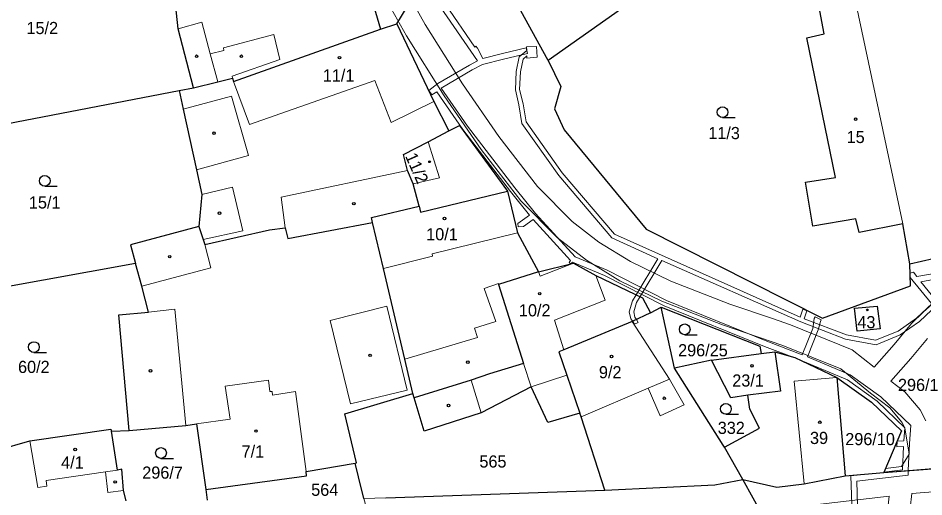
# Model space of a CAD drawing. Extents: x -769392 to -767038, y -1018329 to -1015269.
# Drawn here: x -768574.3 to -768447.4, y -1016273.5 to -1016206.6 of the extents above; entities that cross this region are included whole.
import ezdxf
from ezdxf.enums import TextEntityAlignment as Align

# ---------------------------------------------------------------- set-up
doc = ezdxf.new("R2010")
doc.units = 0
doc.header["$LTSCALE"] = 0.68
for name, color, linetype, lineweight in [('1', 7, 'Continuous', 25), ('13', 7, 'Continuous', 13), ('3', 7, 'Continuous', 25), ('4', 7, 'Continuous', 13), ('5', 7, 'Continuous', 25)]:
    doc.layers.add(name, color=color, linetype=linetype, lineweight=lineweight)
doc.layers.add('2', color=7, linetype='Continuous')

msp = doc.modelspace()

# ---------------------------------------------------------------- linework, layer by layer
at = {"layer": '1'}
for p, q in [((-768464.56, -1016187.45), (-768500.05, -1016212.5)), ((-768500.05, -1016212.5), (-768508.98, -1016196.12)), ((-768551.88, -1016208.04), (-768552.72, -1016199.41)), ((-768521.22, -1016207.35), (-768516.86, -1016200.1)), ((-768525.24, -1016202.34), (-768523.51, -1016208.11)), ((-768461.37, -1016208.75), (-768462.15, -1016204.79)), ((-768523.51, -1016208.11), (-768521.22, -1016207.35)), ((-768521.22, -1016207.35), (-768516.06, -1016218.21)), ((-768549.7, -1016216.3), (-768551.88, -1016208.04)), ((-768544.13, -1016215.41), (-768523.51, -1016208.11)), ((-768463.8, -1016209.3), (-768461.37, -1016208.75)), ((-768459.8, -1016228.85), (-768463.8, -1016209.3)), ((-768500.05, -1016212.5), (-768498.27, -1016216.11)), ((-768546.32, -1016215.48), (-768544.23, -1016214.97)), ((-768544.23, -1016214.97), (-768544.13, -1016215.41)), ((-768551.7, -1016216.69), (-768549.7, -1016216.3)), ((-768549.7, -1016216.3), (-768546.32, -1016215.48)), ((-768498.27, -1016216.11), (-768499.15, -1016219.23)), ((-768592.42, -1016224.53), (-768551.7, -1016216.69)), ((-768551.7, -1016216.69), (-768551.14, -1016219.28)), ((-768516.06, -1016218.21), (-768513.97, -1016222.32)), ((-768551.14, -1016219.28), (-768549.3, -1016227.76)), ((-768499.15, -1016219.23), (-768497.79, -1016222.2)), ((-768516.82, -1016223.86), (-768513.97, -1016222.32)), ((-768513.97, -1016222.32), (-768512.44, -1016221.6)), ((-768512.44, -1016221.6), (-768505.74, -1016230.76)), ((-768497.79, -1016222.2), (-768486.31, -1016236.1)), ((-768520.3, -1016225.66), (-768516.82, -1016223.86)), ((-768519.75, -1016227.87), (-768520.3, -1016225.66)), ((-768549.3, -1016227.76), (-768548.56, -1016231.25)), ((-768518.93, -1016229.73), (-768519.75, -1016227.87)), ((-768463.98, -1016229.5), (-768459.8, -1016228.85)), ((-768518.12, -1016232.87), (-768518.93, -1016229.73)), ((-768462.96, -1016235.68), (-768463.98, -1016229.5)), ((-768548.56, -1016231.25), (-768548.94, -1016235.73)), ((-768517.91, -1016233.72), (-768505.74, -1016230.76)), ((-768505.74, -1016230.76), (-768504.34, -1016236.59)), ((-768524.8, -1016234.47), (-768518.12, -1016232.87)), ((-768518.12, -1016232.87), (-768517.91, -1016233.72)), ((-768536.52, -1016237.38), (-768524.66, -1016235.14)), ((-768524.66, -1016235.14), (-768524.8, -1016234.47)), ((-768523.12, -1016241.57), (-768524.66, -1016235.14)), ((-768456.94, -1016234.65), (-768462.96, -1016235.68)), ((-768456.49, -1016236.57), (-768456.94, -1016234.65)), ((-768548.94, -1016235.73), (-768558.51, -1016238.26)), ((-768548.94, -1016235.73), (-768548.36, -1016237.55)), ((-768548.14, -1016238.23), (-768539.08, -1016236.16)), ((-768539.08, -1016236.16), (-768536.88, -1016235.89)), ((-768536.88, -1016235.89), (-768536.52, -1016237.38)), ((-768504.34, -1016236.59), (-768501.37, -1016242.06)), ((-768486.31, -1016236.1), (-768461.6, -1016248.53)), ((-768450.36, -1016235.36), (-768456.49, -1016236.57)), ((-768449.37, -1016240.92), (-768450.36, -1016235.36)), ((-768548.36, -1016237.55), (-768548.14, -1016238.23)), ((-768558.51, -1016238.26), (-768557.84, -1016240.9)), ((-768449.37, -1016240.92), (-768441.25, -1016239.08)), ((-768557.84, -1016240.9), (-768589.35, -1016246.59)), ((-768556.95, -1016244.04), (-768557.84, -1016240.9)), ((-768520.12, -1016254.29), (-768523.12, -1016241.57)), ((-768501.37, -1016242.06), (-768496.48, -1016240.86)), ((-768496.48, -1016240.86), (-768493.37, -1016242.55)), ((-768449.31, -1016244), (-768449.37, -1016240.92)), ((-768501.37, -1016242.06), (-768506.97, -1016243.83)), ((-768493.37, -1016242.55), (-768486.82, -1016245.68)), ((-768556, -1016247.72), (-768556.95, -1016244.04)), ((-768506.97, -1016243.83), (-768503.51, -1016254.88)), ((-768461.6, -1016248.53), (-768449.31, -1016244)), ((-768486.82, -1016245.68), (-768485.71, -1016247.77)), ((-768560.19, -1016248.07), (-768556, -1016247.72)), ((-768485.71, -1016247.77), (-768488.26, -1016249.01)), ((-768485.71, -1016247.77), (-768484.23, -1016247)), ((-768482.36, -1016255.54), (-768484.23, -1016247)), ((-768484.23, -1016247), (-768470.39, -1016252.44)), ((-768457.11, -1016247.14), (-768453.94, -1016246.86)), ((-768456.77, -1016250.36), (-768457.11, -1016247.14)), ((-768453.94, -1016246.86), (-768453.53, -1016250.04)), ((-768558.72, -1016264.24), (-768560.19, -1016248.07)), ((-768488.26, -1016249.01), (-768497.82, -1016252.96)), ((-768453.53, -1016250.04), (-768456.77, -1016250.36)), ((-768497.82, -1016252.96), (-768498.52, -1016253.25)), ((-768470.39, -1016252.44), (-768470.19, -1016253.48)), ((-768518.99, -1016259.09), (-768520.12, -1016254.29)), ((-768498.52, -1016253.25), (-768497.4, -1016256.52)), ((-768477.14, -1016254.4), (-768470.19, -1016253.48)), ((-768470.19, -1016253.48), (-768468.3, -1016253.25)), ((-768468.3, -1016253.25), (-768465.47, -1016254.05)), ((-768468.3, -1016253.25), (-768467.52, -1016258.75)), ((-768465.47, -1016254.05), (-768459.62, -1016256.85)), ((-768503.51, -1016254.88), (-768508.27, -1016256.32)), ((-768477.14, -1016254.4), (-768482.36, -1016255.54)), ((-768475.52, -1016266.32), (-768482.36, -1016255.54)), ((-768474.43, -1016259.66), (-768477.14, -1016254.4)), ((-768508.27, -1016256.32), (-768510.83, -1016257.2)), ((-768497.4, -1016256.52), (-768495.58, -1016261.82)), ((-768459.62, -1016256.85), (-768458.42, -1016270.59)), ((-768459.62, -1016256.85), (-768454.76, -1016260.29)), ((-768510.83, -1016257.2), (-768518.82, -1016259.7)), ((-768502.44, -1016258.14), (-768509.41, -1016261.8)), ((-768500.06, -1016263.13), (-768502.44, -1016258.14)), ((-768528.52, -1016261.93), (-768518.99, -1016259.09)), ((-768518.82, -1016259.7), (-768518.99, -1016259.09)), ((-768472.06, -1016259.32), (-768474.43, -1016259.66)), ((-768467.52, -1016258.75), (-768472.06, -1016259.32)), ((-768471.81, -1016261.28), (-768472.06, -1016259.32)), ((-768517.38, -1016264.36), (-768518.82, -1016259.7)), ((-768454.76, -1016260.29), (-768450.56, -1016264.31)), ((-768526.87, -1016268.77), (-768528.52, -1016261.93)), ((-768509.41, -1016261.8), (-768517.38, -1016264.36)), ((-768495.58, -1016261.82), (-768500.06, -1016263.13)), ((-768495.4, -1016262.34), (-768495.58, -1016261.82)), ((-768470.45, -1016263.93), (-768471.81, -1016261.28)), ((-768492.08, -1016272.62), (-768495.4, -1016262.34)), ((-768572.62, -1016265.7), (-768561.29, -1016264.07)), ((-768561.29, -1016264.07), (-768561.2, -1016264.37)), ((-768561.2, -1016264.37), (-768558.72, -1016264.24)), ((-768560.34, -1016269.81), (-768561.2, -1016264.37)), ((-768558.72, -1016264.24), (-768550.8, -1016263.56)), ((-768550.8, -1016263.56), (-768549.28, -1016263.33)), ((-768549.28, -1016263.33), (-768547.99, -1016272.52)), ((-768475.36, -1016266.59), (-768470.45, -1016263.93)), ((-768450.56, -1016264.31), (-768453.04, -1016270.15)), ((-768586.47, -1016269.73), (-768572.62, -1016265.7)), ((-768475.36, -1016266.59), (-768475.52, -1016266.32)), ((-768472.78, -1016271.11), (-768475.36, -1016266.59)), ((-768533.93, -1016269.99), (-768527.06, -1016268.82)), ((-768527.06, -1016268.82), (-768526.87, -1016268.77)), ((-768526.59, -1016270.75), (-768527.06, -1016268.82)), ((-768453.04, -1016270.15), (-768438.59, -1016268.98)), ((-768559.76, -1016269.68), (-768560.34, -1016269.81)), ((-768559.49, -1016272.66), (-768559.76, -1016269.68)), ((-768547.99, -1016272.52), (-768533.86, -1016270.61)), ((-768533.86, -1016270.61), (-768533.93, -1016269.99)), ((-768525.85, -1016273.77), (-768526.59, -1016270.75)), ((-768464.2, -1016271.71), (-768458.42, -1016270.59)), ((-768458.42, -1016270.59), (-768453.04, -1016270.15)), ((-768492.08, -1016272.62), (-768476.68, -1016271.84)), ((-768476.68, -1016271.84), (-768472.78, -1016271.11)), ((-768472.78, -1016271.11), (-768468.02, -1016272.16)), ((-768469.86, -1016276.35), (-768472.78, -1016271.11)), ((-768468.02, -1016272.16), (-768464.2, -1016271.71)), ((-768559.15, -1016274.1), (-768559.49, -1016272.66)), ((-768547.99, -1016272.52), (-768547.78, -1016273.99)), ((-768522.75, -1016273.66), (-768498.76, -1016272.82)), ((-768498.76, -1016272.82), (-768492.08, -1016272.62))]:
    msp.add_line(p, q, dxfattribs=at)
at = {"layer": '13'}
for points in [[(-768506.93, -1016223.11), (-768512.05, -1016215.74), (-768517.25, -1016207.46), (-768520.98, -1016200.75), (-768527.01, -1016190.22), (-768528.22, -1016188.66), (-768532.37, -1016182.87), (-768540.52, -1016173.96), (-768546.13, -1016167.31), (-768546.34, -1016166.87), (-768548.49, -1016162.47), (-768548.7, -1016152.45), (-768551.52, -1016145.96), (-768556.22, -1016138.29), (-768560.24, -1016130.3), (-768565.36, -1016119.48), (-768569.27, -1016111.41), (-768572.99, -1016103.31), (-768575.19, -1016097.78), (-768577.71, -1016091.86), (-768578.82, -1016089.6), (-768579.58, -1016087.11), (-768582.55, -1016087.86)], [(-768523.65, -1016202.25), (-768519.89, -1016209.02), (-768514.61, -1016217.44), (-768509.41, -1016224.92), (-768503.87, -1016232.12), (-768498.72, -1016237.29), (-768494.69, -1016240.44), (-768489.98, -1016243.31), (-768484.1, -1016246.16), (-768475.62, -1016249.47), (-768467.19, -1016252.34), (-768459.03, -1016255.63), (-768454.9, -1016259.05), (-768452.19, -1016261.07), (-768450.49, -1016263.09), (-768450.06, -1016263.88), (-768449.49, -1016267.55), (-768450.54, -1016269.3), (-768452.78, -1016269.55), (-768453.04, -1016270.15), (-768438.59, -1016268.98)], [(-768515.11, -1016205.02), (-768509.94, -1016212.51), (-768511.07, -1016213.12), (-768515.49, -1016215.7), (-768516.77, -1016216.66), (-768516.31, -1016217.28), (-768515.63, -1016216.87), (-768511.99, -1016222.14), (-768505.32, -1016230.8), (-768502.65, -1016234.11), (-768504.28, -1016235.3), (-768504.24, -1016235.78), (-768503.5, -1016235.72), (-768502.14, -1016234.72), (-768496.89, -1016240.46), (-768497.1, -1016240.75), (-768496.84, -1016240.94), (-768496.65, -1016240.68), (-768492.13, -1016242.57), (-768483.8, -1016246.8), (-768469.72, -1016252.48), (-768466.23, -1016253.83), (-768465.47, -1016254.05), (-768464.58, -1016254.48), (-768464.39, -1016254.55), (-768458.12, -1016257.17), (-768453.97, -1016260.17), (-768450.08, -1016263.88), (-768450.2, -1016265.68), (-768451.17, -1016265.74), (-768451.18, -1016265.77), (-768451.2, -1016266.54), (-768450.25, -1016266.49), (-768450.39, -1016269.77), (-768453.01, -1016270.08), (-768453.04, -1016270.15), (-768449.6, -1016269.87), (-768449.43, -1016266.08), (-768449.26, -1016263.56), (-768453.45, -1016259.56), (-768457.73, -1016256.47), (-768463.72, -1016253.96), (-768462.22, -1016250.19), (-768461.9, -1016248.98), (-768461.79, -1016248.76), (-768462.66, -1016248.33), (-768462.77, -1016248.56), (-768462.99, -1016249.97), (-768464.46, -1016253.66), (-768469.43, -1016251.74), (-768483.47, -1016246.07), (-768491.79, -1016241.84), (-768496.27, -1016239.95), (-768501.82, -1016233.88), (-768504.69, -1016230.31), (-768511.34, -1016221.66), (-768515.02, -1016216.35), (-768510.68, -1016213.81), (-768509.21, -1016213.03), (-768506.29, -1016212.31), (-768502.94, -1016211.49), (-768503.13, -1016210.71), (-768506.43, -1016211.52), (-768509.19, -1016212.19), (-768509.95, -1016210.76), (-768510.16, -1016210.5), (-768510.29, -1016210.6), (-768514.46, -1016204.55)], [(-768443.36, -1016243.78), (-768448.43, -1016248.53), (-768451.04, -1016250.36), (-768454.18, -1016251.63), (-768458.24, -1016250.88), (-768464.16, -1016248.61), (-768463.79, -1016247.5), (-768464.35, -1016247.28), (-768464.72, -1016248.38), (-768490.75, -1016236.8), (-768498.08, -1016228.2), (-768503.14, -1016221.08), (-768503.56, -1016218.56), (-768504.03, -1016216.52), (-768503.93, -1016214.09), (-768503.55, -1016212.29), (-768503.01, -1016211.85), (-768503.01, -1016212.14), (-768501.58, -1016212.04), (-768501.68, -1016210.51), (-768503.05, -1016210.58), (-768503.03, -1016211.09), (-768504.09, -1016211.96), (-768504.52, -1016214.02), (-768504.63, -1016216.57), (-768504.15, -1016218.68), (-768503.71, -1016221.31), (-768498.55, -1016228.57), (-768491.11, -1016237.29), (-768484.68, -1016240.25), (-768487.71, -1016245.25), (-768487.17, -1016245.51), (-768484.13, -1016240.49), (-768464.64, -1016249.06), (-768458.4, -1016251.46), (-768454.11, -1016252.25), (-768450.75, -1016250.89), (-768448.05, -1016249), (-768442.98, -1016244.25)], [(-768445.06, -1016245.52), (-768447.47, -1016247.67), (-768449.15, -1016249.27), (-768451.57, -1016252.22), (-768454.36, -1016255.38), (-768457.48, -1016252.95), (-768466.11, -1016249.48), (-768468.64, -1016248.58), (-768474.58, -1016246.59), (-768482.87, -1016243.36), (-768488.51, -1016240.61), (-768492.95, -1016237.92), (-768496.68, -1016234.99), (-768501.55, -1016230.1), (-768506.93, -1016223.11)], [(-768442.41, -1016241.66), (-768448.42, -1016242.72), (-768448.89, -1016242.11), (-768449.34, -1016242.22), (-768449.33, -1016242.84), (-768446.37, -1016246.5)], [(-768445.77, -1016245.98), (-768447.85, -1016243.43), (-768442.23, -1016242.44)], [(-768447.12, -1016262.9), (-768447.95, -1016261.35), (-768450.07, -1016258.83), (-768452.03, -1016257.37), (-768449.23, -1016254.2), (-768446.9, -1016251.36)], [(-768438.59, -1016268.98), (-768453.04, -1016270.15), (-768458.42, -1016270.59), (-768464.2, -1016271.71), (-768468.02, -1016272.16), (-768472.78, -1016271.11), (-768470.32, -1016275.52), (-768452.26, -1016273.45), (-768452.82, -1016278.43), (-768450.31, -1016295.22), (-768450.12, -1016319.52), (-768449.71, -1016331.77), (-768449.58, -1016335.6), (-768448.17, -1016335.38), (-768448.24, -1016327), (-768448.89, -1016315.19), (-768449.5, -1016298.7), (-768449.71, -1016295.97), (-768450.07, -1016285.71), (-768449.8, -1016279.21), (-768449.1, -1016273.07), (-768429.05, -1016271.47)], [(-768456.66, -1016276.52), (-768456.82, -1016271.33), (-768449.63, -1016270.49), (-768449.6, -1016269.87), (-768453.04, -1016270.15), (-768454.99, -1016270.31), (-768457.64, -1016270.62), (-768457.47, -1016275.91)]]:
    msp.add_lwpolyline(points, dxfattribs=at)
for points in [[(-768488.68, -1016247.66), (-768488.44, -1016248.63), (-768488.2, -1016248.98), (-768487.68, -1016248.73), (-768487.88, -1016248.41), (-768488.06, -1016247.67), (-768487.67, -1016246.33), (-768487.17, -1016245.51), (-768487.71, -1016245.25), (-768488.22, -1016246.09)], [(-768487.96, -1016249.38), (-768487.44, -1016249.12), (-768487.68, -1016248.73), (-768488.2, -1016248.98), (-768488.12, -1016249.1)], [(-768488.6, -1016275.46), (-768471.55, -1016275.66), (-768470.32, -1016275.52), (-768472.78, -1016271.11), (-768476.68, -1016271.84), (-768492.08, -1016272.62), (-768498.76, -1016272.82), (-768522.75, -1016273.66), (-768525.85, -1016273.77), (-768525.07, -1016276.6), (-768517.45, -1016276.37)]]:
    msp.add_lwpolyline(points, close=True, dxfattribs=at)
at = {"layer": '3'}
for p, q in [((-768475.613, -1016220.47), (-768473.863, -1016220.47)), ((-768570.543, -1016230.07), (-768568.793, -1016230.07)), ((-768480.913, -1016250.85), (-768479.163, -1016250.85)), ((-768572.063, -1016253.33), (-768570.313, -1016253.33)), ((-768475.143, -1016261.98), (-768473.393, -1016261.98)), ((-768554.263, -1016268.15), (-768552.513, -1016268.15))]:
    msp.add_line(p, q, dxfattribs=at)
for centre in [(-768475.6129, -1016219.7198), (-768570.5429, -1016229.3198), (-768480.9129, -1016250.0998), (-768572.0629, -1016252.5798), (-768475.1429, -1016261.2298), (-768554.2629, -1016267.3998)]:
    msp.add_circle(centre, 0.75, dxfattribs=at)
at = {"layer": '4'}
for p, q in [((-768457.02, -1016203.95), (-768450.36, -1016235.36)), ((-768551.88, -1016208.04), (-768548.54, -1016207.1)), ((-768548.54, -1016207.1), (-768547.36, -1016211.56)), ((-768545.53, -1016210.7), (-768538.46, -1016208.86)), ((-768538.46, -1016208.86), (-768537.64, -1016212.33)), ((-768547.36, -1016211.56), (-768545.48, -1016211.1)), ((-768545.48, -1016211.1), (-768545.53, -1016210.7)), ((-768547.36, -1016211.56), (-768546.32, -1016215.48)), ((-768537.64, -1016212.33), (-768544.31, -1016214.67)), ((-768544.31, -1016214.67), (-768544.23, -1016214.97)), ((-768544.13, -1016215.41), (-768541.85, -1016221.43)), ((-768541.85, -1016221.43), (-768524.3, -1016215.26)), ((-768524.3, -1016215.26), (-768522.02, -1016221.16)), ((-768544.39, -1016217.47), (-768551.14, -1016219.28)), ((-768541.99, -1016225.8), (-768544.39, -1016217.47)), ((-768522.02, -1016221.16), (-768516.06, -1016218.21)), ((-768516.82, -1016223.86), (-768515.25, -1016228.91)), ((-768549.3, -1016227.76), (-768541.99, -1016225.8)), ((-768519.75, -1016227.87), (-768537.43, -1016231.63)), ((-768515.25, -1016228.91), (-768518.93, -1016229.73)), ((-768544.23, -1016230.23), (-768548.56, -1016231.25)), ((-768542.82, -1016236.31), (-768544.23, -1016230.23)), ((-768537.43, -1016231.63), (-768536.88, -1016235.89)), ((-768548.36, -1016237.55), (-768542.82, -1016236.31)), ((-768504.34, -1016236.59), (-768516.3, -1016239.55)), ((-768547.26, -1016241.48), (-768548.14, -1016238.23)), ((-768516.22, -1016239.87), (-768523.12, -1016241.57)), ((-768516.3, -1016239.55), (-768516.22, -1016239.87)), ((-768556.95, -1016244.04), (-768547.26, -1016241.48)), ((-768501.15, -1016242.68), (-768496.48, -1016240.86)), ((-768501.37, -1016242.06), (-768501.15, -1016242.68)), ((-768492.03, -1016246.02), (-768493.37, -1016242.55)), ((-768509.02, -1016244.38), (-768507, -1016243.7)), ((-768507, -1016243.7), (-768506.97, -1016243.83)), ((-768507.36, -1016249.02), (-768509.02, -1016244.38)), ((-768499.16, -1016248.8), (-768492.03, -1016246.02)), ((-768552.31, -1016247.27), (-768556, -1016247.72)), ((-768550.8, -1016263.56), (-768552.31, -1016247.27)), ((-768522.62, -1016246.85), (-768530.58, -1016248.86)), ((-768519.78, -1016258.59), (-768522.62, -1016246.85)), ((-768530.58, -1016248.86), (-768527.73, -1016260.54)), ((-768510.37, -1016249.92), (-768507.36, -1016249.02)), ((-768497.82, -1016252.96), (-768499.16, -1016248.8)), ((-768483.06, -1016257.08), (-768488.26, -1016249.01)), ((-768509.93, -1016251.22), (-768510.37, -1016249.92)), ((-768520.12, -1016254.29), (-768509.93, -1016251.22)), ((-768503.51, -1016254.88), (-768502.44, -1016258.14)), ((-768502.44, -1016258.14), (-768497.4, -1016256.52)), ((-768459.62, -1016256.85), (-768465.56, -1016257.36)), ((-768545.26, -1016258.07), (-768539.19, -1016257.23)), ((-768544.59, -1016262.67), (-768545.26, -1016258.07)), ((-768539.19, -1016257.23), (-768539, -1016258.8)), ((-768509.41, -1016261.8), (-768510.83, -1016257.2)), ((-768486.02, -1016258.35), (-768483.06, -1016257.08)), ((-768483.06, -1016257.08), (-768481, -1016260.65)), ((-768465.56, -1016257.36), (-768464.2, -1016271.71)), ((-768539, -1016258.8), (-768538.69, -1016258.78)), ((-768538.69, -1016258.78), (-768538.64, -1016259.29)), ((-768538.64, -1016259.29), (-768535.44, -1016258.8)), ((-768535.44, -1016258.8), (-768533.93, -1016269.99)), ((-768527.73, -1016260.54), (-768519.78, -1016258.59)), ((-768495.4, -1016262.34), (-768486.02, -1016258.35)), ((-768484.34, -1016262.19), (-768486.02, -1016258.35)), ((-768481, -1016260.65), (-768484.34, -1016262.19)), ((-768549.28, -1016263.33), (-768544.59, -1016262.67)), ((-768572.62, -1016265.7), (-768571.51, -1016272.21)), ((-768570.34, -1016271.26), (-768562.04, -1016270.06)), ((-768562.04, -1016270.06), (-768560.34, -1016269.81)), ((-768562.04, -1016270.06), (-768561.72, -1016272.92)), ((-768571.51, -1016272.21), (-768570.27, -1016272.03)), ((-768570.27, -1016272.03), (-768570.34, -1016271.26)), ((-768561.72, -1016272.92), (-768559.49, -1016272.66))]:
    msp.add_line(p, q, dxfattribs=at)
at = {"layer": '5'}
for centre, radius in [((-768549.2668, -1016211.8892), 0.175), ((-768543.0068, -1016211.8892), 0.175), ((-768529.2568, -1016212.0792), 0.175), ((-768456.9768, -1016220.6892), 0.175), ((-768546.8368, -1016222.6492), 0.175), ((-768516.6446, -1016226.6594), 0.1172), ((-768527.2468, -1016232.5192), 0.175), ((-768546.0668, -1016233.8392), 0.175), ((-768514.5568, -1016234.5892), 0.175), ((-768553.0468, -1016239.9392), 0.175), ((-768501.2168, -1016245.1192), 0.175), ((-768455.3446, -1016247.3794), 0.1172), ((-768524.9768, -1016253.7292), 0.175), ((-768491.1568, -1016253.8992), 0.175), ((-768511.2868, -1016254.6992), 0.175), ((-768471.4868, -1016255.2092), 0.175), ((-768555.7268, -1016255.9092), 0.175), ((-768513.9868, -1016260.7592), 0.175), ((-768483.7668, -1016259.7392), 0.175), ((-768461.9868, -1016263.0992), 0.175), ((-768540.9568, -1016264.3292), 0.175), ((-768566.2868, -1016266.9192), 0.175), ((-768560.6868, -1016271.4492), 0.175)]:
    msp.add_circle(centre, radius, dxfattribs=at)

# ---------------------------------------------------------------- texts
at = {"layer": '2'}
for s, p in [('15/2', (-768570.889, -1016208.785)), ('11/1', (-768529.389, -1016215.425)), ('11/3', (-768475.399, -1016223.485)), ('15', (-768456.969, -1016224.035)), ('15/1', (-768570.549, -1016233.195)), ('10/1', (-768514.909, -1016237.645)), ('10/2', (-768501.919, -1016248.285)), ('43', (-768455.469, -1016249.945)), ('296/25', (-768478.36, -1016253.875)), ('60/2', (-768572.069, -1016256.205)), ('9/2', (-768491.35, -1016256.945)), ('23/1', (-768472.039, -1016258.105)), ('296/1', (-768448.2, -1016258.725)), ('332', (-768474.389, -1016264.735)), ('39', (-768462.099, -1016266.145)), ('296/10', (-768454.95, -1016266.305)), ('7/1', (-768541.39, -1016268.035)), ('4/1', (-768566.67, -1016269.575)), ('565', (-768507.769, -1016269.435)), ('296/7', (-768554.04, -1016270.995)), ('564', (-768531.329, -1016273.395))]:
    msp.add_text(s, height=1.7, dxfattribs=at).set_placement(p, align=Align.CENTER)
msp.add_text('11/2', height=1.7, rotation=294, dxfattribs=at).set_placement((-768519.1994, -1016227.8783), align=Align.CENTER)

doc.saveas('drawing.dxf')
